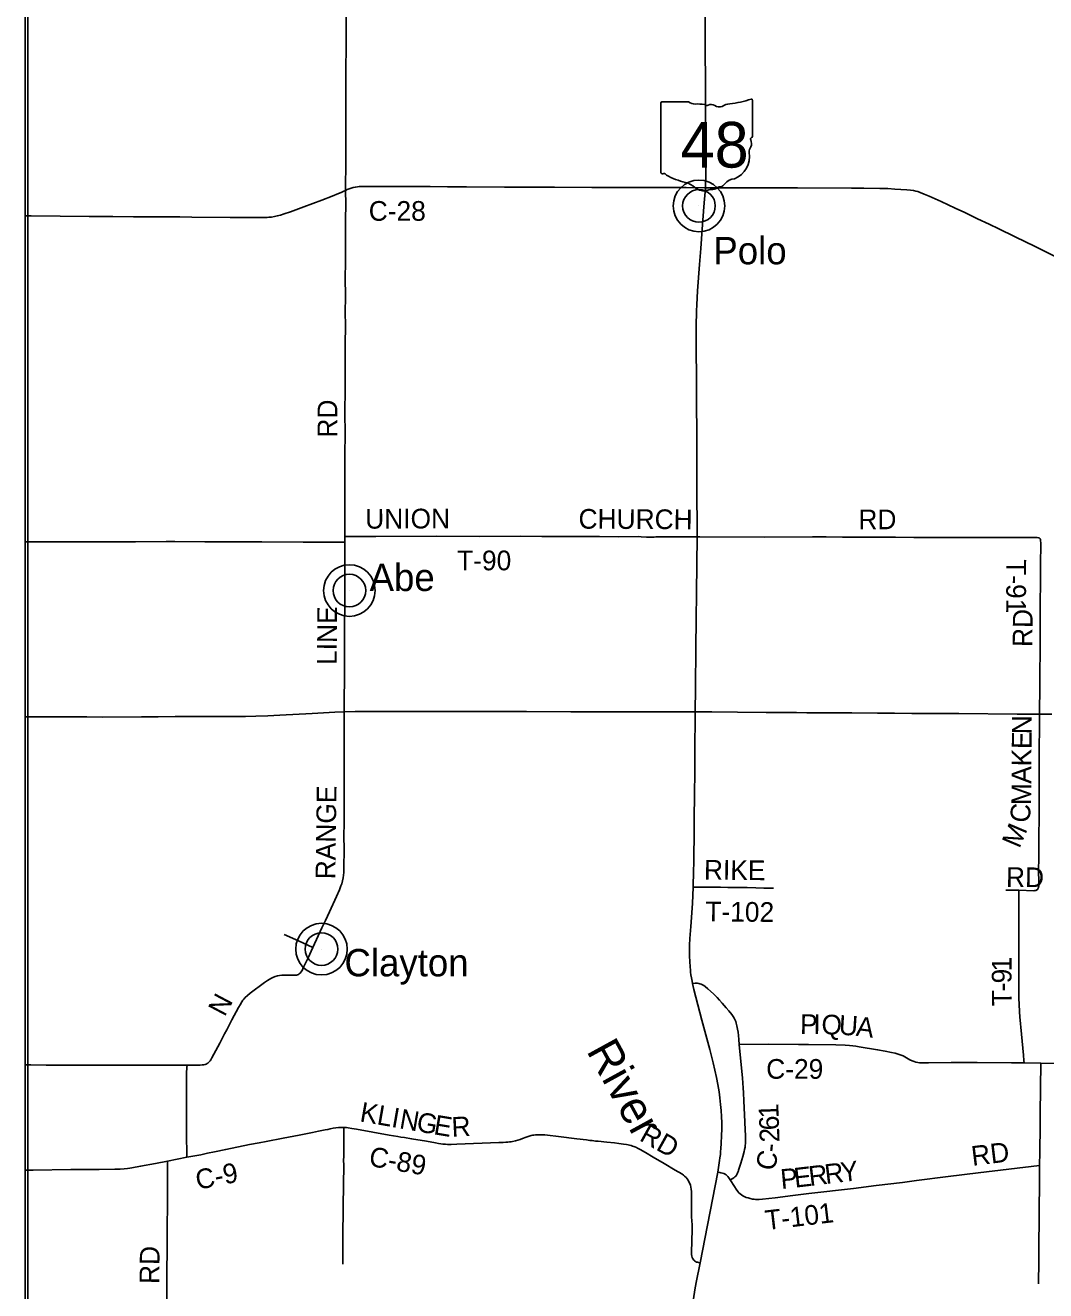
# Model space of a CAD drawing. Extents: x -87 to 2145, y -2128 to 440.
# Drawn here: x 90.3 to 168, y -563.5 to -467.2 of the extents above; entities that cross this region are included whole.
import ezdxf

# ---------------------------------------------------------------- set-up
doc = ezdxf.new("R2010")
doc.units = 0
for name, color, linetype in [('GM_X_Adjacent_County', 7, 'Continuous'), ('GM_X_County', 7, 'Continuous'), ('GM_X_County_Road', 7, 'Continuous'), ('GM_X_County_Road_Text', 7, 'Continuous'), ('GM_X_Major_River_Text', 7, 'Continuous'), ('GM_X_State_Location', 7, 'Continuous'), ('GM_X_State_Route', 7, 'Continuous'), ('GM_X_State_Shield', 7, 'Continuous'), ('GM_X_Township', 7, 'Continuous'), ('GM_X_Township_Road', 7, 'Continuous'), ('GM_X_Township_Road_Text', 7, 'Continuous'), ('GM_X_Unincorporated', 7, 'Continuous'), ('GM_X_Unincorporated_Location', 7, 'Continuous'), ('GM_X_Unincorporated_Text', 7, 'Continuous'), ('SH_Border', 7, 'Continuous')]:
    doc.layers.add(name, color=color, linetype=linetype)

msp = doc.modelspace()

# ---------------------------------------------------------------- linework, layer by layer
at = {"layer": 'GM_X_Adjacent_County'}
msp.add_lwpolyline([(90.326, -451.873), (90.326, -655.29), (342.126, -655.29), (342.126, -461.349)], dxfattribs=at)
at = {"layer": 'GM_X_County'}
msp.add_lwpolyline([(90.326, -451.873), (90.326, -655.29), (342.126, -655.29), (342.126, -461.349)], dxfattribs=at)
at = {"layer": 'GM_X_County_Road'}
for points in [[(114.719, -479.74), (114.715, -479.165), (114.723, -478.05), (114.725, -475.721), (114.729, -474.359), (114.735, -471.21), (114.751, -468.126), (114.761, -465.272), (114.773, -462.991), (114.771, -461.286), (114.769, -460.154), (114.772, -458.661), (114.779, -456.758), (114.791, -455.364), (114.792, -453.806), (114.792, -452.755)], [(90.326, -481.679), (90.783, -481.682), (95.179, -481.723), (95.786, -481.725), (97, -481.735), (98.575, -481.742), (102.101, -481.763), (103.003, -481.768), (105.939, -481.791), (108.203, -481.803), (108.596, -481.797), (108.749, -481.79), (108.873, -481.783), (109.068, -481.764), (109.294, -481.731), (109.517, -481.684), (109.754, -481.622), (110.051, -481.53), (110.515, -481.37), (111.547, -480.991), (112.897, -480.483), (113.692, -480.175), (114.18, -479.982), (114.387, -479.9), (114.594, -479.804), (114.716, -479.742), (114.719, -479.74)], [(114.656, -506.106), (114.658, -504.474), (114.666, -502.883), (114.671, -500.849), (114.669, -499.996), (114.674, -498.126), (114.671, -496.813), (114.68, -494.731), (114.691, -493.615), (114.694, -492.697), (114.696, -491.434), (114.702, -490.072), (114.697, -488.973), (114.698, -487.891), (114.697, -486.283), (114.704, -485.332), (114.708, -484.004), (114.711, -483.265), (114.707, -482.544), (114.71, -481.986), (114.728, -480.789), (114.719, -479.74)], [(114.719, -479.74), (114.849, -479.676), (114.986, -479.617), (115.143, -479.563), (115.303, -479.519), (115.465, -479.487), (115.629, -479.465), (115.748, -479.453), (115.859, -479.447), (116.155, -479.438), (117.255, -479.436), (119.469, -479.446), (121.159, -479.451), (122.488, -479.457), (123.914, -479.468), (126.817, -479.486), (130.622, -479.504), (133.46, -479.509), (135.51, -479.512), (138.02, -479.517), (139.086, -479.522), (140.168, -479.525), (140.66, -479.525), (142.053, -479.532), (142.114, -479.532)], [(142.114, -479.532), (145.317, -479.531), (146.646, -479.533), (149.123, -479.547), (153.24, -479.566), (154.174, -479.576), (155.405, -479.586), (155.715, -479.596), (156.012, -479.605), (156.536, -479.632), (157.453, -479.698), (157.748, -479.725), (157.977, -479.757), (158.155, -479.792), (158.299, -479.83), (158.472, -479.888), (158.777, -480.012), (159.168, -480.183), (160.064, -480.592), (161.136, -481.088), (161.864, -481.429), (162.841, -481.894), (163.73, -482.318), (164.454, -482.666), (165.663, -483.257), (166.535, -483.675), (167.142, -483.966), (167.595, -484.197), (168.815, -484.802)], [(114.616, -519.436), (114.618, -518.876), (114.626, -516.547), (114.628, -515.808), (114.63, -515.333), (114.632, -514.283), (114.637, -512.676), (114.647, -511.56), (114.653, -509.493), (114.651, -508.755), (114.656, -506.521)], [(114.656, -506.521), (114.656, -506.106)], [(112.23, -537.399), (112.911, -535.902), (113.177, -535.34), (113.479, -534.686), (114.013, -533.522), (114.246, -532.998), (114.364, -532.708), (114.424, -532.536), (114.483, -532.33), (114.536, -532.088), (114.565, -531.892), (114.581, -531.694), (114.587, -531.593), (114.587, -531.445), (114.598, -529.792), (114.594, -529.056), (114.602, -527.762), (114.617, -526.551), (114.614, -526.093), (114.616, -525.092), (114.612, -524.436), (114.617, -522.943), (114.62, -522.009), (114.62, -521.024), (114.618, -520.138), (114.616, -519.436)], [(110.03, -536.408), (111.122, -536.887), (112.23, -537.399)], [(102.66, -546.361), (103.436, -546.347), (103.636, -546.346), (103.801, -546.338), (103.914, -546.325), (104.013, -546.305), (104.094, -546.278), (104.17, -546.24), (104.221, -546.208), (104.28, -546.163), (104.338, -546.101), (104.394, -546.03), (104.447, -545.95), (104.53, -545.806), (105.128, -544.675), (105.508, -543.967), (105.668, -543.662), (106.059, -542.907), (106.561, -541.973), (106.68, -541.759), (106.822, -541.521), (106.893, -541.414), (106.966, -541.328), (107.078, -541.213), (107.247, -541.06), (107.46, -540.883), (108.547, -540.064), (108.771, -539.9), (108.894, -539.822), (109.036, -539.745), (109.184, -539.678), (109.351, -539.614), (109.521, -539.563), (109.696, -539.525), (109.873, -539.502), (110.017, -539.494), (110.164, -539.492), (110.312, -539.492), (110.526, -539.502), (110.675, -539.51), (110.858, -539.508), (110.981, -539.494), (111.067, -539.471), (111.123, -539.441), (111.193, -539.4), (111.255, -539.347), (111.321, -539.267), (111.399, -539.138), (111.524, -538.885), (111.864, -538.192), (112.23, -537.399)], [(142.102, -540.369), (141.993, -540.288), (141.894, -540.227), (141.803, -540.183), (141.707, -540.15), (141.608, -540.129), (141.507, -540.119), (141.425, -540.115), (141.341, -540.118), (141.136, -540.146)], [(144.702, -544.781), (144.668, -544.404), (144.637, -544.087), (144.607, -543.849), (144.571, -543.605), (144.523, -543.362), (144.473, -543.17), (144.426, -543.028), (144.369, -542.89), (144.308, -542.772), (144.237, -542.659), (144.121, -542.498), (143.906, -542.228), (143.704, -541.99), (143.405, -541.642), (143.199, -541.412), (143.007, -541.212), (142.724, -540.928), (142.303, -540.537), (142.113, -540.378), (142.102, -540.369)], [(144.628, -554.393), (144.64, -554.358), (144.807, -553.826), (144.959, -553.323), (145.065, -552.943), (145.107, -552.767), (145.136, -552.604), (145.153, -552.49), (145.17, -552.309), (145.178, -552.128), (145.178, -551.947), (145.168, -551.7), (145.149, -551.307), (145.119, -550.669), (145.046, -549.08), (145.02, -548.457), (145.003, -548.08), (144.981, -547.72), (144.946, -547.328), (144.871, -546.577), (144.702, -544.781)], [(144.702, -544.781), (146.899, -544.768), (149.208, -544.788), (149.962, -544.793), (152.057, -544.815), (152.755, -544.842), (153.086, -544.861), (153.336, -544.885), (153.564, -544.912), (153.835, -544.958), (155.235, -545.183), (155.815, -545.294), (156.28, -545.386), (156.566, -545.454), (156.801, -545.518), (157.017, -545.589), (157.181, -545.656), (157.311, -545.722), (157.696, -545.94), (157.859, -546.02), (158.013, -546.08), (158.157, -546.122), (158.286, -546.149), (158.434, -546.168), (158.583, -546.177), (158.813, -546.174), (159.107, -546.168), (160.829, -546.146), (162.814, -546.142), (165.422, -546.168), (166.398, -546.173)], [(90.326, -546.336), (90.745, -546.342), (91.926, -546.347), (94.218, -546.345), (96.07, -546.353), (97.872, -546.357), (100.689, -546.361), (102.66, -546.361)], [(102.629, -553.372), (102.614, -551.495), (102.605, -547.598), (102.604, -547.088), (102.608, -546.945), (102.611, -546.811), (102.622, -546.684), (102.637, -546.539), (102.66, -546.361)], [(166.398, -546.173), (167.652, -546.192)], [(167.652, -546.192), (169.949, -546.22), (172.213, -546.238), (177.217, -546.26), (178.857, -546.267), (180.955, -546.275)], [(114.59, -551.103), (114.473, -551.101), (114.34, -551.101), (114.176, -551.114), (113.978, -551.137), (113.783, -551.165), (113.547, -551.209), (113.354, -551.248), (113.154, -551.289), (112.644, -551.392), (112.198, -551.477), (111.185, -551.678), (109.965, -551.915), (108.677, -552.163), (108.145, -552.263), (107.405, -552.41), (105.589, -552.774), (104.738, -552.95), (104.192, -553.067), (103.695, -553.173), (102.629, -553.372)], [(114.513, -561.5), (114.509, -560.399), (114.517, -559.547), (114.536, -557.106), (114.572, -553.909), (114.573, -553.801), (114.569, -553.763), (114.571, -553.142), (114.581, -552.617), (114.59, -551.103)], [(114.59, -551.103), (114.677, -551.107), (114.794, -551.116), (114.903, -551.132), (115.187, -551.177), (115.539, -551.237), (116.789, -551.456), (118.027, -551.677), (118.699, -551.798), (118.931, -551.831), (119.21, -551.875), (119.738, -551.961), (120.881, -552.157), (121.559, -552.275), (121.785, -552.315), (121.964, -552.344), (122.127, -552.367), (122.337, -552.385), (122.473, -552.389), (122.627, -552.389), (122.769, -552.389), (123.195, -552.375), (126.389, -552.257), (126.713, -552.246), (126.928, -552.231), (127.079, -552.219), (127.191, -552.205), (127.317, -552.184), (127.419, -552.168), (127.66, -552.114), (127.835, -552.067), (128.008, -552.011), (128.193, -551.942), (128.479, -551.831), (128.704, -551.753), (128.855, -551.716), (128.963, -551.698), (129.064, -551.682), (129.175, -551.668), (129.274, -551.659), (129.375, -551.654), (129.453, -551.653), (129.642, -551.658), (129.881, -551.673), (130.103, -551.695), (130.933, -551.784), (132.329, -551.96), (133.06, -552.052), (133.32, -552.083), (133.499, -552.104), (133.759, -552.135), (133.955, -552.155), (134.608, -552.223), (135.185, -552.282), (135.525, -552.318), (135.877, -552.361), (136.119, -552.402), (136.246, -552.429), (136.341, -552.45), (136.461, -552.484), (136.564, -552.515), (136.66, -552.55), (136.757, -552.586), (136.86, -552.631), (136.937, -552.665), (137.14, -552.769), (137.554, -553.003), (138.146, -553.354), (138.991, -553.857), (139.828, -554.344), (140.33, -554.638), (140.453, -554.725), (140.539, -554.798), (140.651, -554.915), (140.732, -555.015), (140.804, -555.122), (140.868, -555.234), (140.928, -555.366), (140.977, -555.503), (141.013, -555.643), (141.041, -555.803), (141.058, -555.98), (141.065, -556.192), (141.053, -557.191), (141.052, -557.47), (141.063, -557.914), (141.085, -558.222), (141.104, -558.519), (141.109, -558.689), (141.108, -558.878), (141.065, -560.616), (141.066, -560.692), (141.071, -560.782), (141.088, -560.899), (141.116, -560.997), (141.141, -561.06), (141.183, -561.134), (141.235, -561.202), (141.284, -561.25), (141.339, -561.291), (141.399, -561.325), (141.447, -561.348), (141.508, -561.369), (141.594, -561.388), (141.711, -561.409)], [(90.326, -554.345), (90.917, -554.342), (93.786, -554.315), (95.951, -554.295), (97.132, -554.28), (97.542, -554.269), (97.854, -554.249), (98.116, -554.222), (98.286, -554.2), (98.426, -554.177), (99.104, -554.052), (100.248, -553.836), (101.161, -553.659)], [(101.161, -553.659), (102.629, -553.372)], [(143.061, -554.507), (143.21, -554.531), (143.305, -554.552), (143.424, -554.582), (143.528, -554.617), (143.629, -554.666), (143.698, -554.707), (143.76, -554.758), (143.823, -554.826), (143.915, -554.946), (144.006, -555.09)], [(144.006, -555.09), (144.148, -555.019), (144.281, -554.943), (144.372, -554.871), (144.429, -554.808), (144.477, -554.739), (144.533, -554.636), (144.585, -554.513), (144.628, -554.393)]]:
    msp.add_lwpolyline(points, dxfattribs=at)
at = {"layer": 'GM_X_State_Route'}
for points in [[(141.349, -519.457), (141.368, -517.637), (141.394, -514.554), (141.427, -512.454), (141.451, -510.355), (141.484, -506.119), (141.468, -502.088), (141.459, -499.184), (141.411, -490.834), (141.421, -490.096), (141.444, -488.915), (141.463, -488.455), (141.529, -487.374), (141.666, -485.377), (141.769, -484.151), (141.872, -482.679), (142.007, -480.978), (142.114, -479.532), (142.122, -479.424), (142.135, -479.179), (142.142, -478.901), (142.142, -478.229), (142.133, -476.08), (142.123, -473.455), (142.126, -471.897), (142.119, -470.7), (142.113, -469.814), (142.097, -468.026), (142.095, -466.55)], [(90.326, -519.827), (90.989, -519.83), (92.515, -519.832), (94.024, -519.834), (95.008, -519.84), (96.222, -519.843), (99.174, -519.829), (100.438, -519.826), (101.75, -519.815), (104.752, -519.809), (106.294, -519.809), (107.082, -519.801), (107.881, -519.778), (108.803, -519.749), (109.705, -519.707), (112.162, -519.569), (113.897, -519.467), (114.616, -519.436), (115.437, -519.413), (117.438, -519.415), (120.653, -519.411), (122.113, -519.425), (124.475, -519.432), (125.508, -519.431), (128.494, -519.431), (131.873, -519.44), (133.333, -519.437), (137.465, -519.452), (139.024, -519.451), (141.349, -519.457)], [(141.218, -564.151), (141.324, -563.47), (141.423, -562.904), (141.709, -561.422), (141.711, -561.409), (142.281, -558.542), (143.061, -554.507), (143.201, -553.626), (143.23, -553.417), (143.258, -553.171), (143.281, -552.939), (143.3, -552.731), (143.328, -552.307), (143.351, -551.75), (143.361, -551.194), (143.359, -550.751), (143.344, -550.277), (143.317, -549.802), (143.279, -549.345), (143.226, -548.857), (143.161, -548.386), (143.068, -547.821), (142.967, -547.289), (142.847, -546.729), (142.715, -546.187), (142.445, -545.156), (141.85, -542.938), (141.69, -542.335), (141.237, -540.588), (141.136, -540.146), (141.1, -539.962), (141.054, -539.699), (141.021, -539.467), (140.995, -539.274), (140.975, -539.086), (140.96, -538.903), (140.926, -538.444), (140.911, -538.083), (140.907, -537.688), (140.916, -537.212), (140.94, -536.703), (140.999, -535.786), (141.125, -534.036), (141.189, -532.798), (141.222, -531.566), (141.233, -530.956), (141.239, -530.201), (141.262, -529.07), (141.27, -527.462), (141.286, -525.871), (141.307, -523.903), (141.309, -523.083), (141.316, -521.951), (141.345, -520.131), (141.349, -519.457)], [(141.349, -519.457), (142.616, -519.46), (144.551, -519.48), (146.749, -519.496), (149.045, -519.509), (149.832, -519.517), (150.996, -519.525), (152.341, -519.532), (153.26, -519.536), (155.228, -519.551), (155.687, -519.556), (156.524, -519.56), (157.836, -519.563), (159.919, -519.577), (160.755, -519.58), (161.411, -519.584), (165.873, -519.615), (166.611, -519.615), (167.557, -519.62), (168.513, -519.626)]]:
    msp.add_lwpolyline(points, dxfattribs=at)
at = {"layer": 'GM_X_State_Shield'}
for p, q in [((138.734, -473.09), (138.734, -478.373)), ((140.841, -472.999), (138.803, -472.999)), ((145.695, -475.631), (145.695, -472.868)), ((145.695, -475.631), (145.695, -475.631))]:
    msp.add_line(p, q, dxfattribs=at)
for centre, radius, start, end in [((138.814, -473.078), 0.0806, 98.1301, 188.1301), ((141.327, -472.385), 0.782, 231.61951, 271.11188), ((141.586, -475.965), 2.808, 80.48669, 94.98827), ((144.157, -474.612), 1.485, 97.34618, 120.76885), ((143.216, -465.796), 7.382, 275.84447, 288.90645), ((145.618, -472.856), 0.0775, 351.86209, 97.738), ((142.224, -473.051), 0.226, 219.79206, 297.10237), ((142.555, -473.662), 0.469, 54.46668, 119.14113), ((143.161, -472.824), 0.564, 233.85621, 294.82819), ((145.677, -475.834), 0.12, 107.94398, 210.33697), ((144.914, -476.184), 0.72, 340.03296, 23.64957), ((145.613, -475.642), 0.0829, 289.60381, 7.73413), ((143.629, -477.14), 1.846, 292.30889, 8.98584), ((145.973, -476.788), 0.524, 136.8065, 186.92959), ((138.815, -478.384), 0.0814, 171.95839, 258.30661), ((138.827, -477.844), 0.621, 267.33899, 280.60386), ((138.954, -478.678), 0.224, 29.74838, 93.27175), ((141.781, -473.931), 5.331, 240.41292, 257.1985), ((144.408, -479.856), 1.011, 94.40312, 142.57675), ((140.191, -480.746), 1.668, 47.18416, 75.83597), ((141.995, -478.704), 1.058, 230.70037, 286.29184), ((142.607, -480.53), 0.87, 85.69512, 111.20995), ((142.684, -479.099), 0.564, 268.77702, 315.54927), ((143.194, -479.611), 0.159, 65.75173, 132.64842), ((143.127, -478.885), 0.597, 282.87319, 323.27711)]:
    msp.add_arc(centre, radius, start, end, dxfattribs=at)
at = {"layer": 'GM_X_Township'}
msp.add_lwpolyline([(90.326, -451.873), (90.326, -638.912), (100.953, -639.016), (111.479, -639.144), (114.255, -639.152), (127.218, -639.312), (140.406, -639.325), (142.807, -639.317), (144.927, -639.27), (178.921, -639.673), (180.382, -639.676), (193.831, -639.58), (193.148, -599.226), (193.87, -578.272), (194.163, -546.477), (194.423, -519.843), (194.535, -497.733), (194.66, -486.734), (194.487, -479.781), (194.661, -479.612), (194.97, -479.59), (195.138, -479.475), (195.194, -479.257), (195.32, -453.117)], dxfattribs=at)
at = {"layer": 'GM_X_Township_Road'}
msp.add_line((164.992, -533.034), (165.997, -533.04), dxfattribs=at)
for points in [[(90.326, -506.511), (91.505, -506.512), (93.456, -506.509), (98.721, -506.494), (101.051, -506.486), (101.723, -506.486), (103.987, -506.498), (104.84, -506.5), (106.726, -506.502), (108.35, -506.505), (111.483, -506.516), (113.287, -506.523), (114.534, -506.521), (114.656, -506.521)], [(114.656, -506.106), (117.029, -506.091), (121.638, -506.073), (124.95, -506.084), (128.033, -506.08), (129.673, -506.09), (131.609, -506.099), (133.101, -506.106), (134.052, -506.101), (135.494, -506.109), (136.987, -506.108), (137.233, -506.118), (137.625, -506.146), (137.772, -506.152), (137.886, -506.155), (138.032, -506.149), (138.227, -506.134), (138.342, -506.127), (138.506, -506.122), (138.636, -506.119), (138.766, -506.119), (138.945, -506.12), (139.714, -506.117), (141.123, -506.117), (141.484, -506.119)], [(141.484, -506.119), (141.696, -506.12), (146.648, -506.14), (150.287, -506.131), (151.321, -506.131), (152.555, -506.137), (156.11, -506.152), (156.602, -506.155), (157.996, -506.162), (159.488, -506.169), (160.833, -506.167), (162.817, -506.169), (164.932, -506.168), (167.214, -506.166), (167.397, -506.172), (167.483, -506.187), (167.545, -506.207), (167.588, -506.242)], [(167.557, -519.62), (167.556, -519.469), (167.561, -519.109), (167.585, -517.928), (167.593, -516.65), (167.592, -516.224), (167.612, -515.109), (167.61, -513.634), (167.606, -513.257), (167.623, -511.076), (167.635, -509.699), (167.645, -508.895), (167.648, -508.304), (167.655, -506.575), (167.651, -506.433), (167.644, -506.378), (167.635, -506.332), (167.614, -506.283), (167.588, -506.242)], [(165.997, -533.04), (167.12, -533.07), (167.205, -533.066), (167.273, -533.056), (167.323, -533.039), (167.37, -533.014), (167.412, -532.98), (167.445, -532.937), (167.469, -532.889), (167.484, -532.838), (167.496, -532.776), (167.501, -532.711), (167.503, -532.637), (167.495, -531.291), (167.5, -530.8), (167.507, -529.93), (167.513, -529.258), (167.519, -528.733), (167.527, -527.667), (167.538, -524.797), (167.541, -523.256), (167.549, -521.994), (167.561, -520.928), (167.557, -519.993), (167.557, -519.62)], [(141.189, -532.798), (141.328, -532.799), (143.278, -532.812), (143.819, -532.816), (144.114, -532.818), (144.605, -532.821), (144.851, -532.824), (145.293, -532.833), (145.965, -532.849), (146.572, -532.868), (147.317, -532.882)], [(166.398, -546.173), (166.381, -546.008), (166.339, -545.601), (166.182, -544.002), (166.056, -542.664), (166.031, -542.304), (166.003, -541.715), (165.994, -541.289), (165.999, -538.616), (165.995, -536.829), (165.992, -535.255), (165.997, -533.04)], [(167.571, -553.994), (167.585, -552.988), (167.609, -550.987), (167.614, -550.052), (167.637, -548.117), (167.652, -546.192)], [(101.11, -572.827), (101.111, -572.668), (101.115, -571.29), (101.121, -570.109), (101.122, -569.503), (101.112, -567.142), (101.128, -566.651), (101.134, -566.141), (101.126, -565.665), (101.121, -565.502), (101.115, -565.305), (101.111, -565.011), (101.101, -562.852), (101.106, -562.278), (101.112, -561.655), (101.119, -560.825), (101.131, -559.416), (101.139, -558.727), (101.14, -558.498), (101.157, -557.159), (101.161, -555.356), (101.164, -553.882), (101.161, -553.659)], [(144.006, -555.09), (144.325, -555.602), (144.453, -555.79), (144.589, -555.973), (144.675, -556.07), (144.756, -556.148), (144.857, -556.228), (144.965, -556.299), (145.079, -556.36), (145.227, -556.423), (145.365, -556.471), (145.538, -556.516), (145.695, -556.549), (145.826, -556.574), (145.938, -556.587), (146.051, -556.593), (146.213, -556.59), (146.457, -556.572), (147.433, -556.454), (148.784, -556.281), (150.005, -556.142), (153.407, -555.745), (155.131, -555.524), (157.117, -555.281), (158.191, -555.145), (160.599, -554.831), (162.895, -554.549), (167.571, -553.994)], [(167.483, -563.022), (167.501, -561.27), (167.511, -560.385), (167.564, -555.039), (167.571, -553.994)]]:
    msp.add_lwpolyline(points, dxfattribs=at)
at = {"layer": 'GM_X_Unincorporated'}
for centre, radius in [((141.629, -480.919), 1.964), ((141.629, -480.919), 1.245), ((115.007, -510.213), 1.964), ((115.007, -510.213), 1.245), ((112.883, -537.518), 1.964), ((112.883, -537.518), 1.245)]:
    msp.add_circle(centre, radius, dxfattribs=at)
at = {"layer": 'GM_X_Unincorporated_Location'}
for p, q in [((141.629, -480.919), (141.629, -480.919)), ((115.007, -510.213), (115.007, -510.213)), ((112.883, -537.518), (112.883, -537.518))]:
    msp.add_line(p, q, dxfattribs=at)
at = {"layer": 'SH_Border'}
for points in [[(90.326, -234.78), (90.326, -654.78), (90.514, -654.78), (90.514, -234.78)], [(342.126, -654.78), (342.126, -234.78), (90.514, -234.78), (90.514, -654.78)]]:
    msp.add_lwpolyline(points, close=True, dxfattribs=at)

# ---------------------------------------------------------------- texts
at = {"layer": 'GM_X_County_Road_Text'}
for s, rotation, p in [('C-28', 0.00001, (116.479, -482.052)), ('RD', 90, (114.086, -498.564)), ('LINE', 89.69775, (114.042, -515.88)), ('RANGE', 89.22599, (113.931, -532.208)), ('N', 62.15315, (105.508, -542.728)), ('P', 358.97362, (149.318, -543.971)), ('I', 358.96958, (150.33, -543.989)), ('Q', 358.65935, (150.944, -544)), ('U', 356.30732, (152.247, -544.03)), ('A', 352.83048, (153.54, -544.113)), ('C-29', 0.00001, (146.751, -547.392)), ('K', 350.13763, (115.74, -550.631)), ('L', 350.13695, (117.041, -550.857)), ('I', 350.13921, (118.146, -551.049)), ('N', 350.13404, (118.753, -551.155)), ('G', 350.13944, (120.054, -551.381)), ('E', 350.56062, (121.366, -551.609)), ('1', 91.98937, (147.705, -550.368)), ('R', 2.80011, (122.821, -551.814)), ('RD', 330.80433, (137.017, -552.052)), ('6', 91.91541, (147.736, -551.293)), ('2', 91.95734, (147.768, -552.217)), ('C-89', 350.09169, (116.428, -554.015)), ('C', 75.40999, (147.346, -554.491)), ('-', 84.40968, (147.701, -553.045)), ('C-9', 11.30943, (103.455, -555.856))]:
    msp.add_text(s, height=1.5, rotation=rotation, dxfattribs=at).set_placement(p)
at = {"layer": 'GM_X_Major_River_Text'}
msp.add_text('River', height=2.4989, rotation=298.73898, dxfattribs=at).set_placement((133.024, -545.257))
at = {"layer": 'GM_X_State_Location'}
msp.add_text('48', height=0.005, rotation=0.00001, dxfattribs=at).set_placement((140.877, -476.446))
for s in ['s', 'r']:
    msp.add_text(s, height=0.005, dxfattribs=at).set_placement((142.136, -476.082))
at = {"layer": 'GM_X_State_Shield'}
msp.add_text('48', height=3.4805, dxfattribs=at).set_placement((140.236, -478))
at = {"layer": 'GM_X_Township_Road_Text'}
for s, rotation, p in [('UNION', 0.21434, (116.213, -505.497)), ('CHURCH', 359.68861, (132.454, -505.497)), ('RD', 0.00001, (153.769, -505.541)), ('T-90', 0.00001, (123.211, -508.669)), ('T-91', 269.6479, (165.048, -507.819)), ('RD', 89.50996, (167.017, -514.517)), ('N', 89.56649, (166.961, -521.164)), ('E', 89.56708, (166.952, -522.286)), ('K', 89.56467, (166.942, -523.606)), ('A', 89.56649, (166.932, -524.926)), ('M', 89.71179, (166.924, -526.553)), ('C', 83.80217, (166.782, -527.946)), ('M', 67.03138, (166.026, -529.907)), ('RIKE', 359.41765, (142.003, -532.224)), ('RD', 359.51096, (165.007, -532.778)), ('T-102', 359.44517, (142.11, -535.399)), ('1', 89.98968, (165.433, -539.214)), ('9', 89.99081, (165.433, -540.13)), ('-', 90.0278, (165.433, -540.741)), ('T', 90.72687, (165.448, -541.856)), ('RD', 6.94216, (162.46, -554.03)), ('E', 6.56752, (148.944, -555.691)), ('R', 6.82108, (150.066, -555.562)), ('R', 6.82108, (151.289, -555.415)), ('Y', 6.82263, (152.512, -555.269)), ('P', 5.26239, (147.9, -555.787)), ('T-101', 6.74108, (146.754, -558.923)), ('RD', 89.50925, (100.53, -563.027))]:
    msp.add_text(s, height=1.5, rotation=rotation, dxfattribs=at).set_placement(p)
at = {"layer": 'GM_X_Unincorporated_Text'}
for s, p in [('Polo', (142.725, -485.365)), ('Abe', (116.545, -510.247)), ('Clayton', (114.631, -539.595))]:
    msp.add_text(s, height=2.085, rotation=0.00001, dxfattribs=at).set_placement(p)

doc.saveas('drawing.dxf')
